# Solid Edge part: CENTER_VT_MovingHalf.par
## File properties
Author: haileyy
Template: ansi part.par
Last saved by: haileyy
Revision: 1
Application: Solid Edge
Accuracy: 0.990
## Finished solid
Body 1: solid body, 30 faces, 84 edges, 56 vertices.
  Faces by surface: plane 21, cylinder 5, swept 4
  Edges by curve: line 66, circle 10, spline 8
Bounding box of the edges (mm; curved faces can reach further): 160.366 x 31.423 x 3.175, from (12.6093, 260.9194, -3.175) to (172.9749, 292.3421, 0).
Cylindrical faces by radius (mm): R1.5875 x1, R6.35 x2, R6.985 x1, R5935.5128 x1
Planar faces by outward normal: +x 4, +y 2, +z 1, -x 2, -y 2, -z 1, oblique 9
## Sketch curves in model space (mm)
line (27.0519, 263.7982, 0) -> (27.0519, 260.9194, 0)
spline (112.9802, 268.7421, 0) -> (121.6635, 269.724, 0) -> (130.3424, 270.7425, 0)
line (20.5749, 261.3021, 0) -> (20.5749, 263.7982, 0)
line (12.6093, 269.6448, 0) -> (20.5749, 261.3021, 0)
spline (27.052, 260.9174, 0) -> (31.1684, 261.2017, 0) -> (35.284, 261.4967, 0)
spline (36.184, 261.5626, 0) -> (42.9351, 262.0727, 0) -> (49.6842, 262.6091, 0)
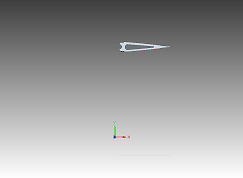
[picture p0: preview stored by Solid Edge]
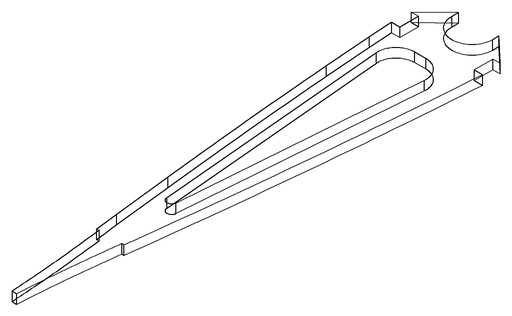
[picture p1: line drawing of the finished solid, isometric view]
